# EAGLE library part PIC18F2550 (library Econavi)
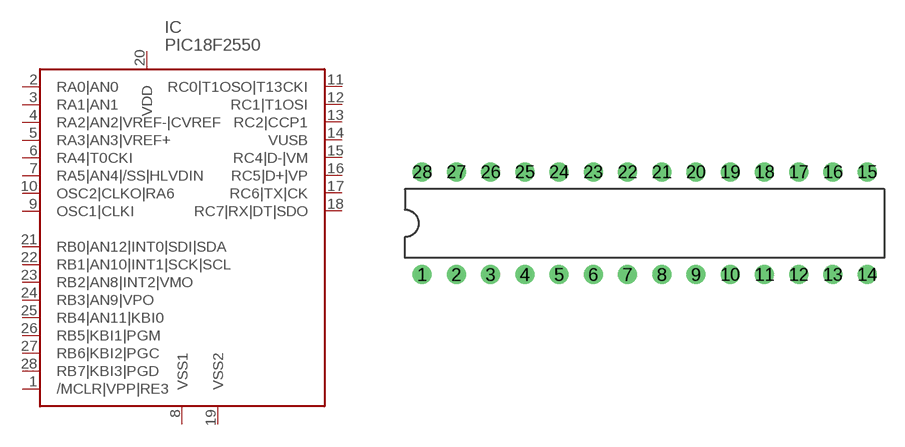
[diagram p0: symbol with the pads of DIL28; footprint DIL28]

Designator prefix IC

## PIC18F2550SP  [DIL28]
1  /MCLR|VPP|RE3
2  RA0|AN0
3  RA1|AN1
4  RA2|AN2|VREF-|CVREF
5  RA3|AN3|VREF+
6  RA4|T0CKI
7  RA5|AN4|/SS|HLVDIN
8  VSS1  pwr
9  OSC1|CLKI
10  OSC2|CLKO|RA6
11  RC0|T1OSO|T13CKI
12  RC1|T1OSI
13  RC2|CCP1
14  VUSB
15  RC4|D-|VM
16  RC5|D+|VP
17  RC6|TX|CK
18  RC7|RX|DT|SDO
19  VSS2  pwr
20  VDD  pwr
21  RB0|AN12|INT0|SDI|SDA
22  RB1|AN10|INT1|SCK|SCL
23  RB2|AN8|INT2|VMO
24  RB3|AN9|VPO
25  RB4|AN11|KBI0
26  RB5|KBI1|PGM
27  RB6|KBI2|PGC
28  RB7|KBI3|PGD

## Footprint DIL28 (pad centres in mm)
Dual In Line Package
drill 0.9 round: 1 -16.51,-3.81; 2 -13.97,-3.81; 3 -11.43,-3.81; 4 -8.89,-3.81; 5 -6.35,-3.81; 6 -3.81,-3.81; 7 -1.27,-3.81; 8 1.27,-3.81; 9 3.81,-3.81; 10 6.35,-3.81; 11 8.89,-3.81; 12 11.43,-3.81; 13 13.97,-3.81; 14 16.51,-3.81; 15 16.51,3.81; 16 13.97,3.81; 17 11.43,3.81; 18 8.89,3.81; 19 6.35,3.81; 20 3.81,3.81; 21 1.27,3.81; 22 -1.27,3.81; 23 -3.81,3.81; 24 -6.35,3.81; 25 -8.89,3.81; 26 -11.43,3.81; 27 -13.97,3.81; 28 -16.51,3.81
